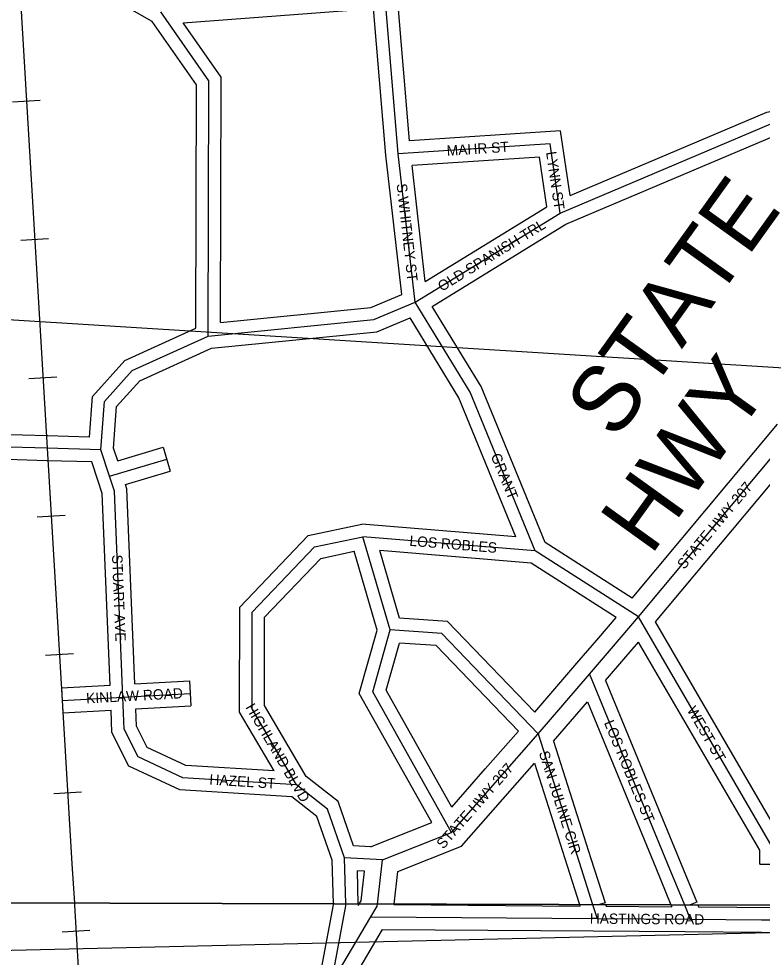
# Model space of a CAD drawing. Extents: x 418523 to 616617, y 1878279 to 2196743.
# Drawn here: x 550209 to 552006, y 2014588 to 2016857 of the extents above; entities that cross this region are included whole.
import ezdxf

# ---------------------------------------------------------------- set-up
doc = ezdxf.new("R2010")
doc.units = 0
for name, color, linetype in [('Level 1', 7, 'Continuous'), ('Level 22', 7, 'Continuous'), ('Level 23', 7, 'Continuous'), ('Level 28', 7, 'Continuous'), ('Level 31', 7, 'Continuous'), ('Level 32', 7, 'Continuous'), ('Level 34', 7, 'Continuous'), ('Level 37', 7, 'Continuous'), ('Level 63', 7, 'Continuous')]:
    doc.layers.add(name, color=color, linetype=linetype)

msp = doc.modelspace()

# ---------------------------------------------------------------- linework, layer by layer
at = {"layer": 'Level 1'}
for p, q in [((545005.963, 2016454.119), (552297.044, 2015997.651)), ((547094.887, 2014533.398), (552313.777, 2014654.627))]:
    msp.add_line(p, q, dxfattribs=at)
at = {"layer": 'Level 22'}
for p, q in [((551706.916, 2015411.178), (552074.874, 2015851.978)), ((551641.724, 2015334.632), (551706.916, 2015411.178)), ((551588.618, 2015272.961), (551641.724, 2015334.632)), ((551464.597, 2015128.579), (551588.618, 2015272.961)), ((551088.457, 2014824.181), (551255.363, 2014890.252)), ((551076.023, 2014717.079), (551088.457, 2014824.181)), ((550965.258, 2014526.333), (551060.168, 2014686.071))]:
    msp.add_line(p, q, dxfattribs=at)
for points in [[(551255.363, 2014890.252), (551366.975, 2015017.215), (551464.597, 2015128.579)], [(551060.168, 2014686.071), (551075.457, 2014712.211), (551076.022, 2014717.079)]]:
    msp.add_lwpolyline(points, dxfattribs=at)
at = {"layer": 'Level 23'}
for p, q in [((551692.302, 2015456.091), (552043.235, 2015876.495)), ((551748.771, 2015398.896), (552086.585, 2015803.584)), ((551611.413, 2015360.734), (551653.237, 2015409.842)), ((551558.307, 2015299.062), (551611.413, 2015360.734)), ((551672.178, 2015308.696), (551707.621, 2015350.311)), ((551456.379, 2015180.4), (551558.275, 2015299.026)), ((551627.641, 2015256.976), (551672.036, 2015308.531)), ((551501.834, 2015110.538), (551583.769, 2015205.925)), ((551059.101, 2014855.581), (551207.435, 2014914.3)), ((551125.432, 2014795.796), (551279.045, 2014856.606)), ((551116.28, 2014716.971), (551125.432, 2014795.796)), ((551029.999, 2014713.722), (551032.033, 2014717.198)), ((551116.125, 2014715.647), (551116.279, 2014716.971)), ((550999.648, 2014505.9), (551088.744, 2014655.851))]:
    msp.add_line(p, q, dxfattribs=at)
for points in [[(551255.586, 2014951.091), (551336.914, 2015043.604), (551416.92, 2015134.871)], [(551279.045, 2014856.606), (551397.036, 2014990.825), (551455.689, 2015057.732)], [(551032.034, 2014717.198), (551036.692, 2014725.162), (551044.937, 2014796.174)]]:
    msp.add_lwpolyline(points, dxfattribs=at)
at = {"layer": 'Level 31'}
for p, q in [((551126.625, 2016530.009), (551094.13, 2016913.401)), ((551493.389, 2016554.05), (551126.625, 2016530.009)), ((551517.95, 2016387.059), (551493.389, 2016554.05)), ((551167.116, 2016171.322), (551126.625, 2016530.009)), ((551167.116, 2016171.322), (551517.95, 2016387.059)), ((550277.4, 2015818.589), (549693.955, 2015834.466)), ((550407.653, 2015814.94), (550277.4, 2015818.589)), ((550428.703, 2015750.874), (550407.653, 2015814.94)), ((550428.703, 2015750.874), (550566.692, 2015792.297)), ((551457.301, 2015570.448), (551040.617, 2015604.736)), ((551106.847, 2015379.44), (551040.617, 2015604.736)), ((551706.916, 2015411.178), (551457.301, 2015570.448)), ((552030.522, 2014854.946), (551706.916, 2015411.178)), ((551588.618, 2015272.961), (551776.85, 2014815.666)), ((550313.99, 2015209.351), (550460.76, 2015217.29)), ((550460.76, 2015217.29), (550623.697, 2015226.275)), ((550880.74, 2015005.155), (550772.871, 2015188.751)), ((551464.597, 2015128.579), (551563.55, 2014818.093)), ((551088.457, 2014824.181), (550996.87, 2014828.446)), ((550999.892, 2014717.285), (550996.87, 2014828.446)), ((551563.55, 2014818.093), (551596.21, 2014715.671)), ((551776.85, 2014815.666), (551818.235, 2014715.071)), ((551596.209, 2014715.671), (551606.975, 2014681.915)), ((551818.234, 2014715.071), (551832.589, 2014680.176)), ((551060.168, 2014686.071), (551606.975, 2014681.915)), ((551606.975, 2014681.915), (551832.589, 2014680.176)), ((551832.589, 2014680.176), (552004.982, 2014679.006)), ((552004.982, 2014679.006), (552485.154, 2014675.46))]:
    msp.add_line(p, q, dxfattribs=at)
for points in [[(550666.751, 2016089.483), (550668.527, 2016706.248), (550552.059, 2016873.141)], [(551517.95, 2016387.059), (552026.93, 2016602.349), (552441.73, 2016690.631)], [(550666.751, 2016089.483), (551067.161, 2016129.788), (551167.116, 2016171.322)], [(551457.301, 2015570.448), (551299.926, 2015954.199), (551167.116, 2016171.322)], [(550407.653, 2015814.94), (550416.23, 2015931.65), (550483.32, 2016006.371), (550666.751, 2016089.483)], [(550460.76, 2015217.29), (550440.643, 2015714.837), (550428.703, 2015750.874)], [(550772.871, 2015188.751), (550773.226, 2015422.221), (550923.911, 2015579.98), (551040.617, 2015604.736)], [(551255.363, 2014890.252), (551064.58, 2015229.733), (551106.847, 2015379.44)], [(551464.597, 2015128.579), (551231.699, 2015370.717), (551106.847, 2015379.44)], [(550497.426, 2015072.811), (550464.022, 2015139.457), (550460.76, 2015217.29)], [(550880.74, 2015005.155), (550605.678, 2015022.313), (550497.426, 2015072.811)], [(550996.87, 2014828.446), (550955.371, 2014946.391), (550880.74, 2015005.155)], [(550965.258, 2014526.333), (551000.023, 2014712.428), (550999.891, 2014717.285)]]:
    msp.add_lwpolyline(points, dxfattribs=at)
at = {"layer": 'Level 32'}
for p, q in [((551154.034, 2016561.87), (551124.073, 2016915.361)), ((550606.8, 2016847.123), (551066.744, 2016881.283)), ((551096.769, 2016527.059), (551066.745, 2016881.284)), ((551519.044, 2016585.795), (551154.034, 2016561.87)), ((551541.988, 2016429.8), (551519.044, 2016585.795)), ((551134.776, 2016190.371), (551096.769, 2016527.059)), ((551467.735, 2016522.303), (551159.965, 2016502.129)), ((551485.393, 2016402.256), (551467.736, 2016522.302)), ((551191.631, 2016221.615), (551159.965, 2016502.128)), ((551191.631, 2016221.615), (551485.393, 2016402.256)), ((551208.326, 2016161.443), (551531.73, 2016360.312)), ((550278.216, 2015848.578), (549694.771, 2015864.455)), ((550379.835, 2015845.73), (550278.24, 2015848.577)), ((550448.079, 2015788.014), (550438.01, 2015818.661)), ((550448.079, 2015788.014), (550558.066, 2015821.031)), ((550558.066, 2015821.031), (550575.319, 2015763.562)), ((550276.585, 2015788.599), (549693.14, 2015804.476)), ((550385.735, 2015785.541), (550276.56, 2015788.6)), ((550400.201, 2015741.51), (550385.735, 2015785.541)), ((550466.89, 2015731.012), (550575.319, 2015763.562)), ((551410.968, 2015604.362), (551038.695, 2015634.996)), ((551075.627, 2015379.271), (551019.67, 2015569.624)), ((551129.747, 2015407.913), (551081.731, 2015571.251)), ((551447.432, 2015541.157), (551081.732, 2015571.251)), ((551692.302, 2015456.091), (551481.452, 2015590.626)), ((551653.237, 2015409.841), (551447.432, 2015541.157)), ((552047.632, 2014885.195), (551748.771, 2015398.896)), ((552000.5, 2014846.892), (551707.62, 2015350.311)), ((550489.507, 2015248.92), (550622.045, 2015256.229)), ((550622.045, 2015256.229), (550625.349, 2015196.319)), ((551627.641, 2015256.976), (551804.594, 2014827.085)), ((550312.37, 2015239.306), (550429.589, 2015245.647)), ((550312.37, 2015239.306), (550315.612, 2015179.393)), ((551583.769, 2015205.925), (551749.108, 2014804.246)), ((550315.612, 2015179.393), (550432.058, 2015185.692)), ((550491.975, 2015188.964), (550625.349, 2015196.319)), ((550903.743, 2015025.227), (550802.885, 2015196.891)), ((550826.289, 2015038.61), (550742.859, 2015180.61)), ((551501.835, 2015110.538), (551592.135, 2014827.202)), ((551455.689, 2015057.733), (551534.965, 2014808.983)), ((551059.101, 2014855.581), (551018.461, 2014857.473)), ((552000.404, 2014813.209), (552000.5, 2014846.892)), ((550969.877, 2014717.366), (550967.01, 2014822.926)), ((551592.133, 2014827.207), (551626.374, 2014719.829)), ((551804.595, 2014827.08), (551848.034, 2014721.493)), ((551534.967, 2014808.978), (551564.694, 2014715.757)), ((551749.106, 2014804.251), (551785.759, 2014715.159)), ((552000.404, 2014813.209), (552060.405, 2014813.039)), ((551044.937, 2014796.174), (551027.738, 2014796.975)), ((551029.906, 2014717.203), (551027.738, 2014796.975)), ((551029.999, 2014713.722), (551029.905, 2014717.203)), ((551116.125, 2014715.647), (551565.818, 2014712.229)), ((551564.693, 2014715.757), (551565.818, 2014712.229)), ((551626.374, 2014719.829), (551613.194, 2014715.626)), ((551627.725, 2014715.587), (551628.95, 2014711.745)), ((551628.95, 2014711.745), (551787.67, 2014710.513)), ((551785.758, 2014715.159), (551787.67, 2014710.513)), ((551832.31, 2014715.034), (551832.309, 2014715.034)), ((551832.311, 2014715.034), (551832.31, 2014715.034)), ((551832.31, 2014715.034), (551832.31, 2014715.034)), ((551832.312, 2014715.034), (551832.311, 2014715.034)), ((551832.313, 2014715.034), (551832.312, 2014715.034)), ((551832.314, 2014715.034), (551832.313, 2014715.034)), ((551832.315, 2014715.034), (551832.314, 2014715.034)), ((551832.316, 2014715.034), (551832.315, 2014715.034)), ((551832.315, 2014715.034), (551832.315, 2014715.034)), ((551832.317, 2014715.034), (551832.316, 2014715.034)), ((551832.318, 2014715.034), (551832.317, 2014715.034)), ((551832.319, 2014715.034), (551832.318, 2014715.034)), ((551832.32, 2014715.034), (551832.319, 2014715.034)), ((551832.321, 2014715.034), (551832.32, 2014715.034)), ((551832.32, 2014715.034), (551832.32, 2014715.034)), ((551832.322, 2014715.034), (551832.321, 2014715.034)), ((551832.323, 2014715.034), (551832.322, 2014715.034)), ((551832.324, 2014715.034), (551832.323, 2014715.034)), ((551832.325, 2014715.034), (551832.324, 2014715.034)), ((551832.326, 2014715.034), (551832.325, 2014715.034)), ((551832.325, 2014715.034), (551832.325, 2014715.034)), ((551832.327, 2014715.034), (551832.326, 2014715.034)), ((551832.328, 2014715.034), (551832.327, 2014715.034)), ((551832.329, 2014715.034), (551832.328, 2014715.034)), ((551832.33, 2014715.034), (551832.329, 2014715.034)), ((551832.331, 2014715.034), (551832.33, 2014715.034)), ((551832.33, 2014715.034), (551832.33, 2014715.034)), ((551832.332, 2014715.034), (551832.331, 2014715.034)), ((551848.034, 2014721.493), (551832.332, 2014715.034)), ((551850.714, 2014714.984), (551852.749, 2014710.037)), ((551852.749, 2014710.037), (552037.987, 2014708.764)), ((551088.743, 2014655.851), (551597.479, 2014651.986)), ((551597.475, 2014651.986), (551819.971, 2014650.26)), ((551820, 2014650.259), (552004.779, 2014649.006)), ((552004.761, 2014649.006), (552484.934, 2014645.459))]:
    msp.add_line(p, q, dxfattribs=at)
for points in [[(550531.332, 2016850.421), (550389.687, 2016931.065), (550381.383, 2017205.569)], [(550636.807, 2016108.851), (550638.499, 2016696.855), (550531.332, 2016850.421)], [(550696.848, 2016122.665), (550698.555, 2016715.642), (550606.8, 2016847.123)], [(551541.988, 2016429.8), (552017.881, 2016631.096), (552435.485, 2016719.974)], [(551531.731, 2016360.311), (552035.978, 2016573.602), (552447.976, 2016661.288)], [(550696.848, 2016122.665), (551059.744, 2016159.194), (551134.775, 2016190.371)], [(551481.453, 2015590.625), (551326.773, 2015967.804), (551208.327, 2016161.443)], [(550674.652, 2016060.126), (551074.579, 2016100.383), (551154.92, 2016133.766)], [(551410.968, 2015604.363), (551273.08, 2015940.593), (551154.92, 2016133.766)], [(550379.835, 2015845.731), (550387.061, 2015944.068), (550465.203, 2016031.099), (550636.806, 2016108.851)], [(550438.01, 2015818.661), (550445.4, 2015919.231), (550501.436, 2015981.643), (550674.652, 2016060.126)], [(550429.589, 2015245.647), (550410.837, 2015709.408), (550400.225, 2015741.439)], [(550489.506, 2015248.92), (550470.449, 2015720.266), (550466.889, 2015731.012)], [(550742.859, 2015180.611), (550743.244, 2015434.266), (550908.619, 2015607.404), (551038.695, 2015634.996)], [(550802.885, 2015196.891), (550803.209, 2015410.176), (550939.204, 2015552.555), (551019.67, 2015569.624)], [(551456.379, 2015180.4), (551245.313, 2015399.84), (551129.748, 2015407.913)], [(551207.435, 2014914.3), (551032.323, 2015225.896), (551075.627, 2015379.271)], [(551255.586, 2014951.091), (551096.838, 2015233.571), (551129.092, 2015347.811)], [(551416.92, 2015134.871), (551218.085, 2015341.595), (551129.091, 2015347.811)], [(550475.285, 2015050.035), (550434.317, 2015131.769), (550432.058, 2015185.692)], [(550519.57, 2015095.584), (550493.727, 2015147.146), (550491.975, 2015188.964)], [(550826.289, 2015038.61), (550613.213, 2015051.902), (550519.57, 2015095.584)], [(550869.534, 2014975.794), (550598.142, 2014992.724), (550475.285, 2015050.035)], [(551018.461, 2014857.472), (550980.778, 2014964.571), (550903.744, 2015025.227)], [(550967.01, 2014822.926), (550929.965, 2014928.212), (550869.534, 2014975.794)], [(550942.059, 2014565.515), (550969.946, 2014714.801), (550969.876, 2014717.366)]]:
    msp.add_lwpolyline(points, dxfattribs=at)
at = {"layer": 'Level 37'}
for p, q in [((550193.577, 2016655.767), (550260.8, 2016659.789)), ((550213.577, 2016321.503), (550280.8, 2016325.525)), ((550233.578, 2015987.239), (550300.8, 2015991.261)), ((550253.615, 2015652.97), (550320.837, 2015657.006)), ((550273.69, 2015318.711), (550340.913, 2015322.747)), ((550293.672, 2014984.46), (550360.895, 2014988.468)), ((550313.74, 2014650.186), (550380.963, 2014654.223))]:
    msp.add_line(p, q, dxfattribs=at)
for points in [[(551085.71, 2020718.422), (550985.474, 2020685.254), (550748.692, 2020555.017), (550593.165, 2020469.641), (550329.897, 2020167.472), (550317.497, 2020153.326), (550124.977, 2019770.219), (550111.681, 2019665.886), (550090.929, 2019503.39), (550081.8, 2019086.659), (550112.939, 2018567.259), (550277.4, 2015818.589), (550313.99, 2015209.351), (550337.57, 2014813.981), (550343.335, 2014719.061)], [(550343.334, 2014719.061), (550343.621, 2014714.321), (550399.569, 2013782.822), (550448.256, 2012969.898), (550641.212, 2009748.759), (550989.714, 2003931.01), (551073.537, 2002534.68), (551165.834, 2000993.953), (551340.764, 1998073.633), (551558.417, 1994442.608), (551575.076, 1994167.635), (551579.618, 1994091.981), (551658.943, 1992768.766), (551979.044, 1987434.09), (552005.691, 1986987.443), (552155.3, 1986052.784), (552752.879, 1982319.616), (553725.111, 1976246.749)]]:
    msp.add_lwpolyline(points, dxfattribs=at)
at = {"layer": 'Level 63'}
for points in [[(537381.015, 2014754.121), (576999.64, 2014646.963), (577097.813, 2060104.5), (537528.7, 2060211.986), (537381.015, 2014754.121)], [(537233.895, 1969297.112), (576901.845, 1969190.287), (576999.639, 2014646.963), (537381.014, 2014754.121), (537233.895, 1969297.112)]]:
    msp.add_lwpolyline(points, dxfattribs=at)

# ---------------------------------------------------------------- texts
at = {"layer": 'Level 28'}
for s, p in [('STATE', (551652.395, 2015835.216)), ('HWY', (551737.02, 2015556.775))]:
    msp.add_text(s, height=160, rotation=54.3091, dxfattribs=at).set_placement(p)
at = {"layer": 'Level 34'}
for s, rotation, p in [('MAHR ST', 3.749669, (551244.352, 2016525.2)), ('LYNN ST', 278.366097, (551483.679, 2016534.175)), ('S.WHITNEY ST', 276.439667, (551122.28, 2016457.082)), ('OLD SPANISH TRL', 31.587692, (551231.97, 2016196.531)), ('GRANT', 292.29735, (551349.482, 2015800.419)), ('STATE HWY 207', 50.145672, (551817.737, 2015524.435)), ('LOS ROBLES', 355.295122, (551152.822, 2015582.964)), ('STUART AVE', 272.314358, (550434.359, 2015560.916)), ('KINLAW ROAD', 3.15555, (550372.535, 2015201.62)), ('HIGHLAND BLVD', 300.434719, (550756.197, 2015192.457)), ('WEST ST', 300.189094, (551823.467, 2015185.989)), ('LOS ROBLES ST', 292.372039, (551623.522, 2015155.329)), ('SAN JULINE CIR', 287.676214, (551466.157, 2015082.525)), ('STATE HWY 207', 48.680289, (551235.294, 2014848.497)), ('HAZEL ST', 356.430028, (550669.345, 2015005.817)), ('HASTINGS ROAD', 359.554789, (551589.334, 2014669.552))]:
    msp.add_text(s, height=25, rotation=rotation, dxfattribs=at).set_placement(p)

doc.saveas('drawing.dxf')
